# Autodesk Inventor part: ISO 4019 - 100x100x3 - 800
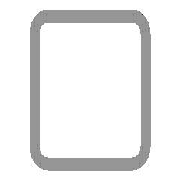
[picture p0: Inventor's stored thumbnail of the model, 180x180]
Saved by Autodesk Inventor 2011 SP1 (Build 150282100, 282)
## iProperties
IsCustomPart: 1
Created: 2010-02
Part Number: ISO 4019 - 100x100x3 - 800
Material: Steel, Mild
Description: Structural steels - Cold-formed, welded, structural hollow sections
Document SubType Name: Modeling
Standard: ISO 4019
Designer: SERGIO
Standard Revision: Second edition 2001-09-01
Standards Organization: ISO
Language: en-US
Size Designation: 100x100x3 - 800
Categories: <MemberInstance><Categories><Category DisplayName="Structural Shapes" InternalName="089c4875-fa83-4c05-b084-43b9cc11f5ed" Mnemonic="GRDR"><CategoryParameter Dis
Stock Number: 100x100x3
Density: 1 g/cm^3
G_L: 800,000 mm
Author: SERGIO
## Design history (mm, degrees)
node "Start plane"
node "End plane"
sketch "Sketch"
  geometry: L1 (-50, -44)-(-50, 44); L2 (-44, 50)-(44, 50); L3 (50, 44)-(50, -44); L4 (44, -50)-(-44, -50); L5 (-44, 47)-(44, 47); L6 (47, 44)-(47, -44); L7 (44, -47)-(-44, -47); L8 (-47, -44)-(-47, 44); L9 (0, 107.32)-(0, -107.32) reference; L10 (-107.32, 0)-(107.32, 0) reference; A1 r 6 centre (-44, -44) between (-50, -44) and (-44, -50); A2 r 6 centre (44, 44) between (50, 44) and (44, 50); A3 r 6 centre (-44, 44) between (-44, 50) and (-50, 44); A4 r 6 centre (44, -44) between (44, -50) and (50, -44); A5 r 3 centre (-44, 44) between (-44, 47) and (-47, 44); A6 r 3 centre (44, 44) between (47, 44) and (44, 47); A7 r 3 centre (44, -44) between (44, -47) and (47, -44); A8 r 3 centre (-44, -44) between (-47, -44) and (-44, -47)
  constraints: 16 end point, 16 point on circle, 8 centre point, 8 tangent, 4 parallel, 3 equal radius, 2 perpendicular, 7 other
  dimensions: "d7" = 6 radius of A1 (= G_IR); "d9" = 100 distance between parallel lines of L1 L3 (= G_W); "d11" = 100 distance between parallel lines of L2 L4 (= G_H); "d12" = 3 distance between parallel lines of L3 L6 (= G_T); "d15" = 50 distance between parallel lines of L9 L3 (= 0.5 x d9); "d16" = 50 distance between parallel lines of L2 L10 (= 0.5 x d11)
extrude "Body" new body sketch "Sketch" stored distance "d3" = 800 (= G_L); taper "d4" = 0 deg
node "Driven Length"
  sketch "Sketch3"
    geometry: L1 (0, 0)-(10, 0) reference
    constraints: 2 end point, 1 horizontal
  workplane "Work Plane3"
  sketch "Sketch4"
    geometry: L1 (-2, 0)-(12, 0) reference; L2 (-2, 800)-(12, 800) reference
    dimensions: "d18" = 800 distance between parallel lines of L1 L2 (derived)
body "Solid1"
other parameters: "G_W" = 100 [user parameter; used in 1 equation term], "G_H" = 100 [user parameter; used in 1 equation term], "G_T" = 3 [user parameter; used in 1 equation term], "G_IR" = 6 [user parameter; used in 1 equation term], "G_L" = 800 (= d18) [user parameter; used in 1 equation term], "G_OFFSET_START" = 0 [user parameter; used in 1 equation term], "G_OFFSET_END" = 0 [user parameter; used in 1 equation term], "d13" = 0 (computed from G_OFFSET_START), "d17" = 90 deg, "MAS" = 0.896 [user parameter]
